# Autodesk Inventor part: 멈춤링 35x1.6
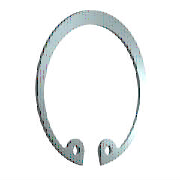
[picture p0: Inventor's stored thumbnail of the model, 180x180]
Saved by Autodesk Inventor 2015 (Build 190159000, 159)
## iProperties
IsCustomPart: 1
Created: 2015-09
Part Number: 멈춤링 35x1.6
Material: 강철, 연강
Description: 리테이닝 링(C형)
Document SubType Name: Modeling
Standard: KS B 1336
Designer: mduedu
Standards Organization: KS
Language: ko-KR
Size Designation: 35x1.6
Categories: <MemberInstance><Categories><Category DisplayName="샤프트 부품" InternalName="7f7aeb1f-a693-4053-b835-cee3144e0d98" Mnemonic="SHFT"><Category DisplayName="써클립" Inter
Density: 7.86 g/cm^3
Mass: 3.5371 g
Surface Area: 9.09651 cm^2
Volume: 0.450013 cm^3
Appearance: 파란색 - 벽 페인트 - 광택
Author: mduedu
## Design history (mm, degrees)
sketch "스케치1"
  geometry: L1 (0, 15.113)-(0, -73.177) reference; L2 (-45.5, 0)-(45.5, 0) reference; L3 (-4.964, 1)-(1.502, 1); L4 (0, -2.5)-(-5.307, -2.5); L5 (0, -17.5)-(-8.583, -33.888); L6 (-8.583, -33.888)-(-21.772, -26.981); L7 (-7.377, -31.585)-(-17.631, -26.214); L8 (-5.162, -32.745)-(-6.29, -34.898); L9 (5.162, -32.745)-(6.29, -34.898); C1 r 1.25 at (-7.377, -31.585); C2 r 1.25 at (7.377, -31.585); A1 r 15.875 centre (0, -18.375) between (11.82, -28.972) and (-11.82, -28.972); A2 r 18.5 centre (0, -17.5) between (6.29, -34.898) and (-6.29, -34.898); A3 r 2.5 centre (-7.377, -31.585) between (-5.162, -32.745) and (-8.668, -29.444); A4 r 2.5 centre (-9.959, -27.303) between (-11.82, -28.972) and (-8.668, -29.444); A5 r 2.5 centre (9.959, -27.303) between (8.668, -29.444) and (11.82, -28.972); A6 r 2.5 centre (7.377, -31.585) between (8.668, -29.444) and (5.162, -32.745); 3 further points
  constraints: 15 point on circle, 14 end point, 9 symmetric about line, 8 centre point, 6 tangent, 4 coincident, 4 point on line, 3 perpendicular, 1 parallel, 4 other
  dimensions: "d8" = 0.875 distance of A1.centre L5.start (= 0.25 x SRB1); "d38" = 3.5 distance between parallel lines of L4 L3 (= SRB1); "d39" = 17.5 distance from line of L5.start L2 (= 0.5 x WD); "d43" = 18.5 radius of A2 (= 0.5 x ND); "d45" = 2.6 distance between parallel lines of L7 L6 (= 0.5 x SRB2); "d46" = 2.5 radius of A4 (= SD5); "d47" = 6.29 distance from line of L1 L8.end (= 0.17 x ND); "d48" = 2.5 diameter of C1 (= SD5); "d49" = 2.5 radius of A3 (= SD5)
extrude "본체" new body sketch "스케치1" distance "d2" = 1.6 (= SD); taper "d3" = 0 deg
workaxis "Work Axis1"
workaxis "Work Axis2"
workplane "Work Plane1"
body "Solid1"
other parameters: "WD" = 35 [user parameter; used in 3 equation terms], "SD" = 1.6 [user parameter; used in 1 equation term], "SRB1" = 3.5 [user parameter; used in 2 equation terms], "ND" = 37 [user parameter; used in 2 equation terms], "SRB2" = 5.2 [user parameter; used in 1 equation term], "SD5" = 2.5 [user parameter; used in 3 equation terms], "d50" = 0, "d51" = 0, "d52" = 0, "d53" = 0, "WDMIN" = 34 [user parameter], "SD6" = 37.8 [user parameter], "WDMAX" = 35 (= WD) [user parameter], "NND" = 35 (= WD) [user parameter]
